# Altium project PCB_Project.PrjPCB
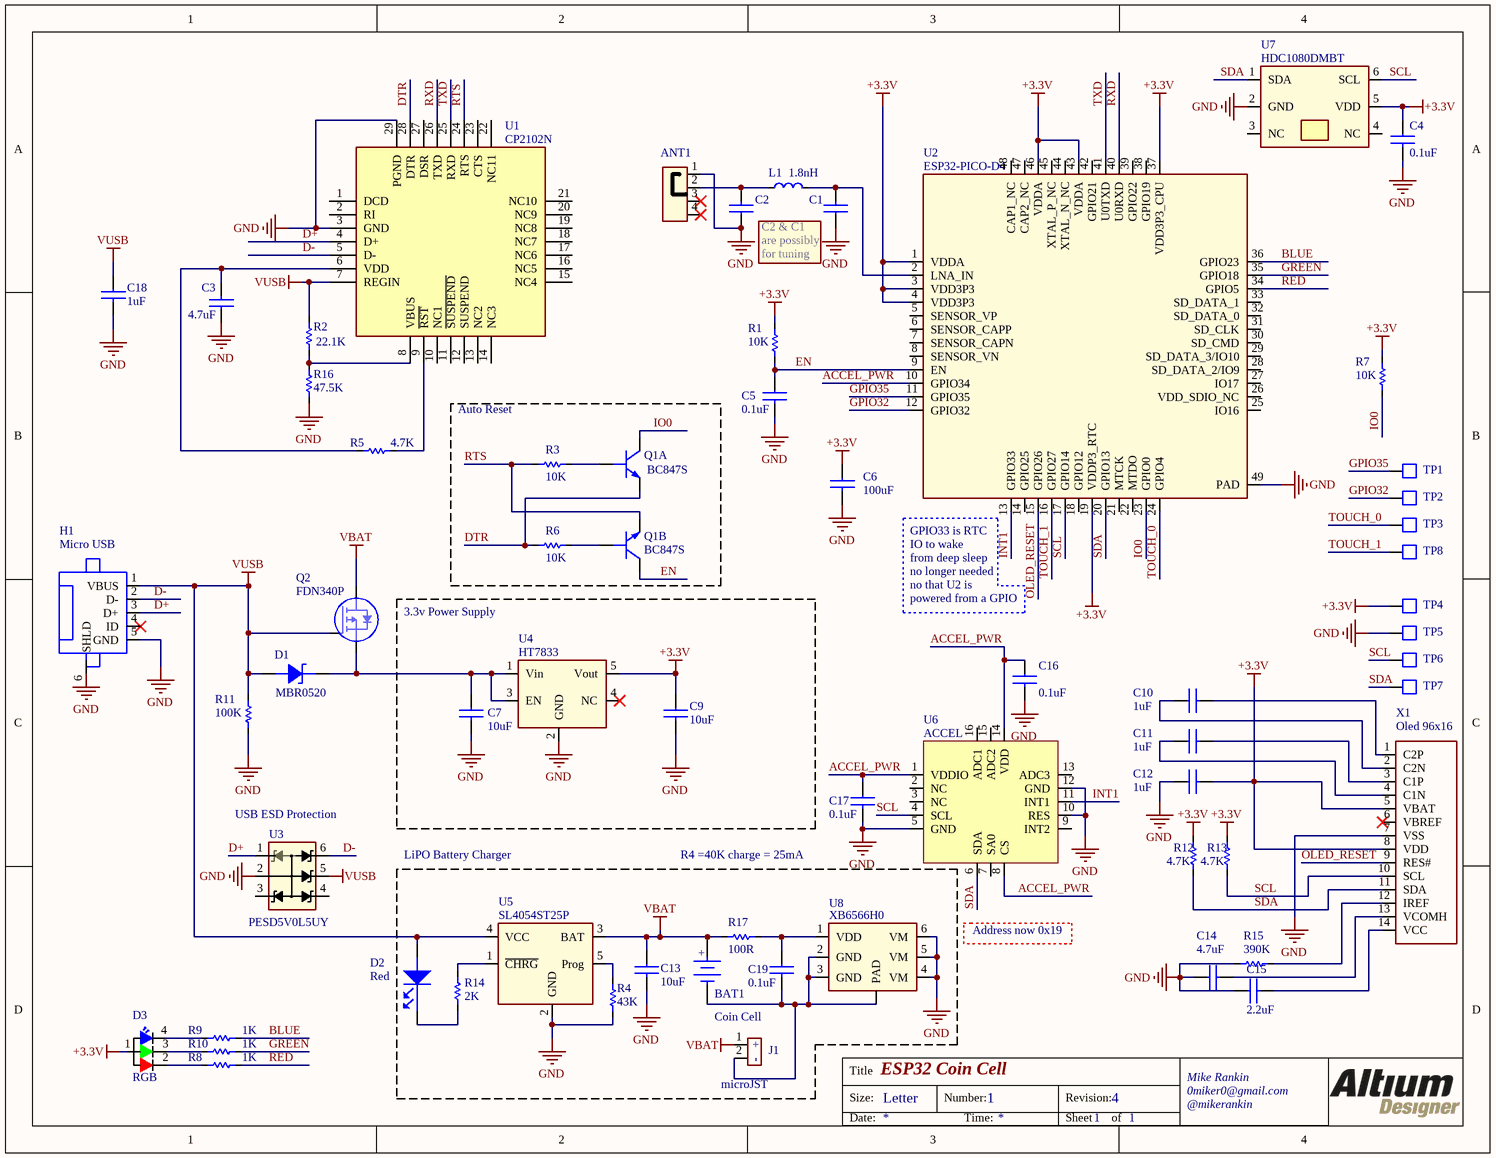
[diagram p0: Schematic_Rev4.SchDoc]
1 sheet, 62 parts. Net scope: global (net labels, ports and power ports of the same name join across sheets).
Board file: PCB_Rev4.PcbDoc

## Sheet Schematic_Rev4.SchDoc: ESP32 Coin Cell
size Letter; DrawnBy: x; Engineer: x; Address1: Mike Rankin; Address2: 0miker0@gmail.com; Address3: @mikerankin; DocumentNumber: 1; Revision: 4; SheetNumber: 1; SheetTotal: 1

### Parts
ANT1  RF ANT 2.4GHZ STAMPED MET SLD  [PRO-OB-440]  (value not drawn)
BAT1  BATTERY-HOLDER (2450)  [BU2450SM-JJ-GTR]  (value not drawn)
C1  (no value)  [CAPC1005X56N]  (no BOM)
C2  (no value)  [CAPC1005X56N]  (no BOM)
C3  4.7uF  [CAPC1005X56N]
C4  0.1uF  [CAPC1005X56N]
C5  0.1uF  [CAPC1005X56N]
C6  100uF  [CAPC3216X160L]
C7  10uF  [CAPC2012X140N]
C9  10uF  [CAPC2012X140N]
C10  1uF  [CAPC1005X56N]
C11  1uF  [CAPC1005X56N]
C12  1uF  [CAPC1005X56N]
C13  10uF  [CAPC2012X140N]
C14  4.7uF  [CAPC1005X56N]
C15  2.2uF  [CAPC1005X56N]
C16  0.1uF  [RESC1005X40L]
C17  0.1uF  [CAPC1005X56N]
C18  1uF  [CAPC1005X56N]
C19  0.1uF  [CAPC1005X56N]
D1  MBR0520  [SOD123]
D2  value Red  [LED1608X55N-RED]  (hidden comment: LED_0603)
D3  RGB  [FC-B1010RGBT-HG]
H1  Micro USB  [1981584-1]
J1  CON2  [JST_Micro_2PIN]  (value not drawn)  (no BOM)
L1  value 1.8nH  [RESC1005X40L]  (hidden comment: Inductor)
Q1  BC847S  [SOT65P210X110-6N]  (parts A,B of 2)
Q2  FDN340P  [SOT95P240X110-3N]
R1  10K  [RESC1005X40L]
R2  22.1K  [RESC1005X40L]
R3  10K  [RESC1005X40L]
R4  43K  [RESC1005X40L]
R5  4.7K  [RESC1005X40L]
R6  10K  [RESC1005X40L]
R7  10K  [RESC1005X40L]
R8  1K  [RESC1005X40L]
R9  1K  [RESC1005X40L]
R10  1K  [RESC1005X40L]
R11  100K  [RESC1005X40L]
R12  4.7K  [RESC1005X40L]
R13  4.7K  [RESC1005X40L]
R14  2K  [RESC1005X40L]
R15  390K  [RESC1005X40L]
R16  47.5K  [RESC1005X40L]
R17  100R  [RESC1005X40L]
TP1  Test Point, 1mm Top Layer  [TP100TL]  (value not drawn)  (no BOM)
TP2  Test Point, 1mm Top Layer  [TP100TL]  (value not drawn)  (no BOM)
TP3  Test Point, 1mm Top Layer  [TP100TL]  (value not drawn)  (no BOM)
TP4  Test Point, 1mm Top Layer  [TP100TL]  (value not drawn)  (no BOM)
TP5  Test Point, 1mm Top Layer  [TP100TL]  (value not drawn)  (no BOM)
TP6  Test Point, 1mm Top Layer  [TP100TL]  (value not drawn)  (no BOM)
TP7  Test Point, 1mm Top Layer  [TP100TL]  (value not drawn)  (no BOM)
TP8  Test Point, 1mm Top Layer  [TP100TL]  (value not drawn)  (no BOM)
U1  CP2102N  [28-QFN]
U2  ESP32-PICO-D4  [QFN48]
U3  PESD5V0L5UY  [SOT65P210X110-6N]
U4  HT7833  [SOT95P280X144-5N]
U5  SL4054ST25P  [SOT95P280X144-5N]
U6  ACCEL  [QFN3X3_16_1.2]
U7  HDC1080DMBT  [HDC1080]
U8  XB6566H0  [DFN-6 2x2mm]
X1  OLED_GLASS 96x16  [OLED_GLASS 96x16]  (value not drawn)

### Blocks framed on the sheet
Auto Reset: Q1 R3 R6
3.3v Power Supply: C7 C9 U4

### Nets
+3.3V: C4.1 C6.1 C9.1 C12.2 D3.1 R1.1 R7.1 R12.1 R13.1 TP4.1 U2.1(VDDA) U2.3(VDD3P3) U2.4(VDD3P3) U2.19(VDDP3_RTC) U2.37(VDD3P3_CPU) U2.43(VDDA) U2.46(VDDA) U4.5(Vout) U7.5(VDD) X1.5(VBAT) X1.8(VDD)
GND: ANT1.1 C1.1 C2.1 C3.1 C4.2 C5.2 C6.2 C7.2 C9.2 C12.1 C13.2 C14.1 C15.1 C16.2 C17.2 C18.2 H1.5(GND) H1.6(SHLD) R4.2 R11.2 R15.1 R16.1 TP5.1 U1.3(GND) U1.29(PGND) U2.49(PAD) U3.2 U4.2(GND) U5.2(GND) U6.5(GND) U6.10(RES) U6.12(GND) U7.2(GND) U8.4(VM) U8.5(VM) U8.6(VM) X1.7(VSS)
VBAT: BAT1.1(+) C13.1 J1.1 Q2.3(D) R17.1 U5.3(BAT)
VUSB: C18.1 D1.2(Annode) D2.2(ANODE) H1.1(VBUS) Q2.1(G) R2.2 R11.1 U1.7(REGIN) U3.5 U5.4(VCC)
ACCEL_PWR: C16.1 C17.1 U2.10(GPIO34) U6.1(VDDIO) U6.8(CS) U6.14(VDD)
BLUE: R9.2 U2.36(GPIO23)
D+: H1.3(D+) U1.4(D+) U3.1
D-: H1.2(D-) U1.5(D-) U3.6
DTR: Q1.1(E1) R6.2 U1.28(DTR)
EN: C5.1 Q1.3(C2) R1.2 U2.9(EN)
GPIO32: TP2.1 U2.12(GPIO32)
GPIO35: TP1.1 U2.11(GPIO35)
GREEN: R10.2 U2.35(GPIO18)
INT1: U2.13(GPIO33) U6.11(INT1)
IO0: Q1.6(C1) R7.2 U2.23(GPIO0)
OLED_RESET: U2.15(GPIO26) X1.9(RES#)
RED: R8.2 U2.34(GPIO5)
RTS: Q1.4(E2) R3.2 U1.24(RTS)
RXD: U1.26(TXD) U2.40(U0RXD)
SCL: R13.2 TP6.1 U2.17(GPIO14) U6.4(SCL) U7.6(SCL) X1.10(SCL)
SDA: R12.2 TP7.1 U2.20(GPIO13) U6.6(SDA) U7.1(SDA) X1.11(SDA)
TOUCH_0: TP3.1 U2.24(GPIO4)
TOUCH_1: TP8.1 U2.16(GPIO27)
TXD: U1.25(RXD) U2.41(U0TXD)
NetANT1_2: ANT1.2 C2.2 L1.1
NetBAT1_2: BAT1.2(-) C19.2 J1.2 U8.2(GND) U8.3(GND) U8.7(PAD)
NetC1_2: C1.2 L1.2 U2.2(LNA_IN)
NetC3_2: C3.2 R5.1 U1.6(VDD)
NetC7_1: C7.1 D1.1(Cathode) Q2.2(S) U4.1(Vin) U4.3(EN)
NetC10_1: C10.1 X1.2(C2N)
NetC10_2: C10.2 X1.1(C2P)
NetC11_1: C11.1 X1.4(C1N)
NetC11_2: C11.2 X1.3(C1P)
NetC14_2: C14.2 X1.13(VCOMH)
NetC15_2: C15.2 X1.14(VCC)
NetC19_1: C19.1 R17.2 U8.1(VDD)
NetD2_1: D2.1(CATHODE) R14.1
NetD3_2: D3.2 R8.1
NetD3_3: D3.3 R10.1
NetD3_4: D3.4 R9.1
NetQ1_2: Q1.2(B1) R3.1
NetQ1_5: Q1.5(B2) R6.1
NetR2_1: R2.1 R16.2 U1.8(VBUS)
NetR4_1: R4.1 U5.5(Prog)
NetR5_2: R5.2 U1.9(~{RST})
NetR14_2: R14.2 U5.1(~{CHRG})
NetR15_2: R15.2 X1.12(IREF)

Not connected (* = marked no-connect by the designer): ANT1 3* 4*; H1 4(ID)*; U1 1(DCD) 2(RI) 10(NC1) 11(~{SUSPEND}) 12(SUSPEND) 13(NC2) 14(NC3) 15(NC4) 16(NC5) 17(NC6) 18(NC7) 19(NC8) 20(NC9) 21(NC10) 22(NC11) 23(CTS) 27(DSR); U2 5(SENSOR_VP) 6(SENSOR_CAPP) 7(SENSOR_CAPN) 8(SENSOR_VN) 14(GPIO25) 18(GPIO12) 21(MTCK) 22(MTDO) 25(IO16) 26(VDD_SDIO_NC) 27(IO17) 28(SD_DATA_2/IO9) 29(SD_DATA_3/IO10) 30(SD_CMD) 31(SD_CLK) 32(SD_DATA_0) 33(SD_DATA_1) 38(GPIO19) 39(GPIO22) 42(GPIO21) 44(XTAL_N_NC) 45(XTAL_P_NC) 47(CAP2_NC) 48(CAP1_NC); U3 3 4; U4 4(NC)*; U6 2(NC) 3(NC) 7(SA0) 9(INT2) 13(ADC3) 15(ADC2) 16(ADC1); U7 3(NC) 4(NC); X1 6(VBREF)*

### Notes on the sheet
- C2 & C1
- are possibly
- for tuning
- (near U2) GPIO33 is RTC
- (near U2) IO to wake
- (near U2) from deep sleep
- no longer needed
- no that U2 is
- powered from a GPIO
- Oled 96x16
- (near U3) USB ESD Protection
- LiPO Battery Charger
- R4 =40K charge = 25mA
- Address now 0x19
- Coin Cell
- (near J1) microJST

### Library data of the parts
ANT1 = PRO-OB-440: Manufacturer: Proant AB; Vendor: Digi-Key
BAT1 = BU2450SM-JJ-GTR: HOLDER,BATT,COIN,24.5MM,SMT; Manufacturer: MPD; Value: Coin Cell Holder; Vendor: LCSC
C1 C2 = CAP_0402: DNP
C3 C14 = CAP_0603: CAP CER 4.7uF 16V 0402; PartNumber: CM05X5R475M16AH; Manufacturer: Kyocera; Vendor: LCSC
C4 C5 C16 C17 C19 = CAP_0402: CAP CER 0.1uF 16V 0402; PartNumber: TCC0402X5R104M160AT; Manufacturer: CCTC; Vendor: LCSC
C6 = CAP_1206: CAP CER 100uF 6.3V 1206; PartNumber: JMK316BJ107ML-T; Manufacturer: Taiyo Yuden; Vendor: LCSC
C7 C9 = CAP_0805: CAP 10uF 0805; Manufacturer: Murata; PartNumber: GRM21BB31C106KE15L; Vendor: LCSC
C10-C12 C18 = CAP_0603: CAP CER 1uF 16V 0402; PartNumber: GRM155R61C105KA12D; Manufacturer: Murata; Vendor: LCSC
C13 = CAP_0805: CAP CER 10uF 16V 0805; PartNumber: CL21A106KOQNNNG; Manufacturer: Samsung; Vendor: LCSC
C15 = CAP_0402: CAP CER 2.2uF 16V 0402; PartNumber: CL05A225KO5NQNC; Manufacturer: Samsung; Vendor: LCSC
D1 = MBR0520-TP: DIODE SCHOTTKY 20V 500MA SOD123; Manufacturer: CJ; Vendor: LCSC
D2 = LED_0603: LED RED CLEAR 0603 SMD; Manufacturer: FNO; PartNumber: FC-DA1608HRK-620D; Vendor: LCSC
D3 = FC-B1010RGBT-HG: LED,RGB LED,SMD,RoHS; Manufacturer: Foshan; Vendor: LCSC; Value: RGB Led
H1 = 1981584-1: CONN RCPT MICRO USB TYPE AB; Manufacturer: REG CON; PartNumber: C21377; Vendor: LCSC
J1 = JST_Micro_CONN_2PIN: JST MIcro CONN 2POS
L1 = Inductor: Inductor 1.8nH 0402; PartNumber: BKW0603UC1N8KGT; Manufacturer: GFBE; Vendor: LCSC
Q1 = BC847S: TRANS 2NPN 44V 0.1A SC-70-6; Manufacturer: Changjiang; Vendor: LCSC
Q2 = FDN340P: MOSFET P-CH 20V 2A SOT-23; Manufacturer: On Semi; Vendor: LCSC; Value: Mosfet P-H
R1 R3 R6 R7 = RES_0402: RES SMD 10K OHM 0402; PartNumber: RC-02W1002FT; Manufacturer: Guangdong; Vendor: LCSC
R2 = RES_0603: RES SMD 22.1K OHM 0402; Manufacturer: Yageo; PartNumber: RC0402FR-0722K1L; Vendor: LCSC
R4 = RES_0603: RES SMD 43K OHM 0402; Manufacturer: Uniroyal; PartNumber: 0402WGF4302TCE; Vendor: LCSC
R5 R12 R13 = RES_0603: RES SMD 4.7K OHM 0402; Manufacturer: Yageo; PartNumber: RC0402FR-074K7L; Vendor: LCSC
R8-R10 = RES_0402: RES SMD 1K OHM 0402; PartNumber: RC0402FR-071KL; Manufacturer: Yageo; Vendor: LCSC
R11 = RES_0603: RES SMD 100K OHM 0402; Manufacturer: Uniroyal Elec; PartNumber: 0402WGF1003TCE; Vendor: LCSC
R14 = RES_0603: RES SMD 2K OHM 1% 1/10W 0402; Manufacturer: LIZ Elec; PartNumber: CR0402FF2001G; Vendor: LCSC
R15 = RES_0603: RES SMD 390K OHM 0402; Manufacturer: Guangdong; PartNumber: RC-02W3903FT; Vendor: LCSC
R16 = RES_0603: RES SMD 47.5K OHM 0402; Manufacturer: Yageo; PartNumber: RC0402FR-0747K5L; Vendor: LCSC
R17 = RES_0603: RES SMD 100R OHM 1% 1/10W 0402; Manufacturer: Yageo; PartNumber: RC0402FR-07100RL; Vendor: LCSC
U1 = CP2102N: IC BRIDGE USB TO UART 28QFN; Manufacturer: Silicon Labs; PartNumber: CP2102N-A01-GQFN28; Vendor: LCSC
U2 = ESP32-PICO-D4: RF Transceiver ICs QFN-48_7x7x05P RoHS; Manufacturer: Espressif; Vendor: LCSC
U3 = PESD5V0L5UY: TVS SOT-363 RoHS; Manufacturer: Yenji; Vendor: LCSC; Value: ESD
U4 = HT7833: IC LDO 3.3V 0.5A SOT23-5; Manufacturer: Holtek; Vendor: LCSC
U5 = SL4054ST25P: Charger IC Lithium-Ion/Polymer SOT23-5; Manufacturer: Techfuse; Vendor: LCSC
U6 = E-05-177: IC ACCEL 2-16G I2C/SPI 16LGA; PartNumber: LIS3DHTR; Manufacturer: STMicro; Vendor: LCSC; Value: LIS3DHTR
U7 = HDC1080DMBT: Humidity/Temperature Sensor; Manufacturer: Texas Instruments; Vendor: LCSC
U8 = XB6566H0: IC Battery Protection; Manufacturer: XySemi; Vendor: LCSC
X1 = OLED_GLASS 96x16: 96x16 OLED_GLASS; PartNumber: ER-OLED0.69-1W; Vendor: Buy-Display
